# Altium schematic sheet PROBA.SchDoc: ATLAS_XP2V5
size 558 x 431 mm; Organization: IMP Automatika d.o.o.; Revision: V5
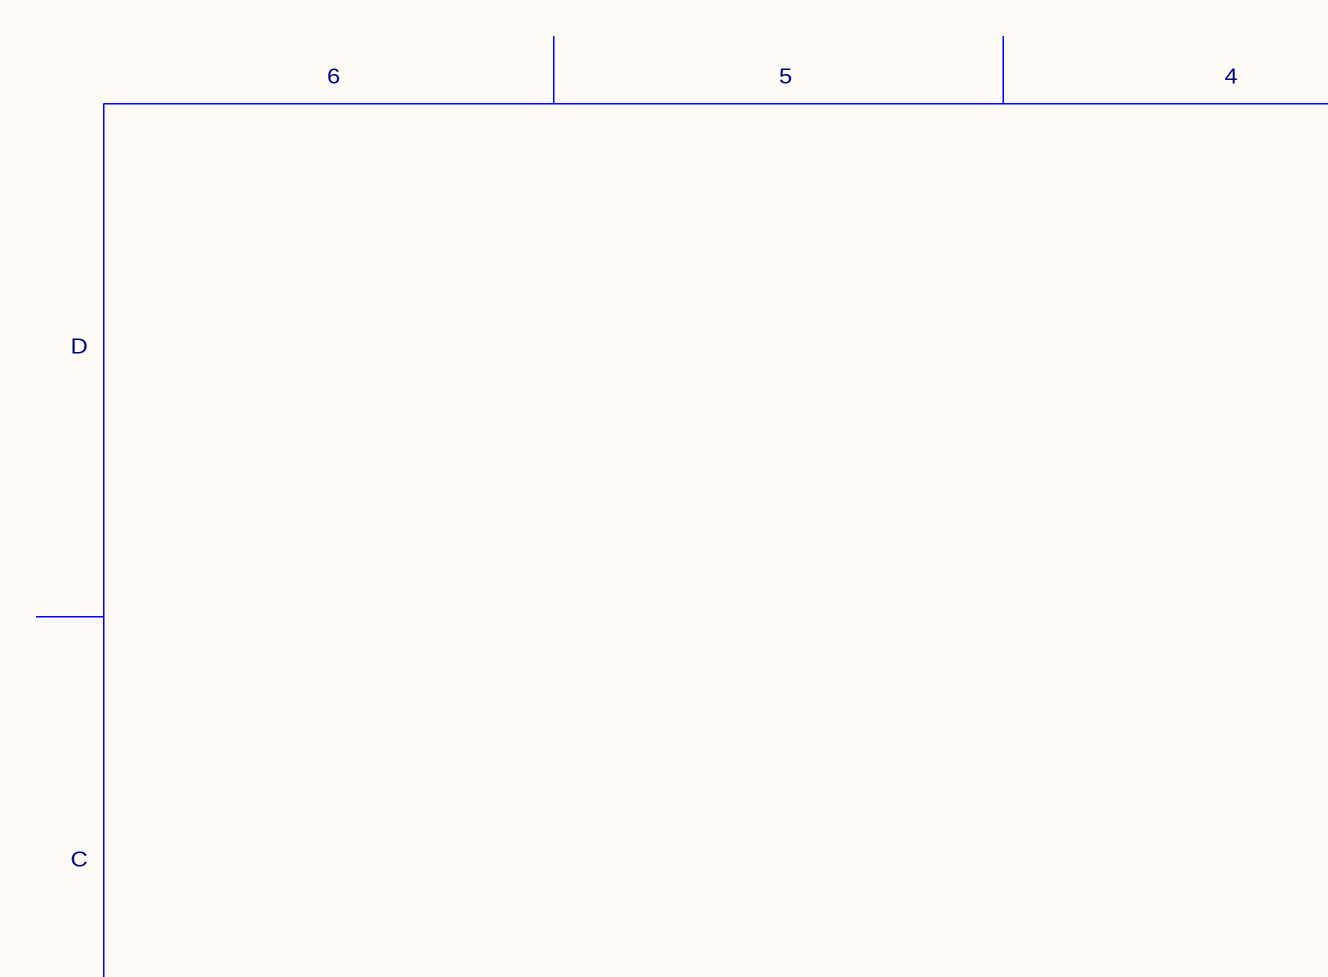
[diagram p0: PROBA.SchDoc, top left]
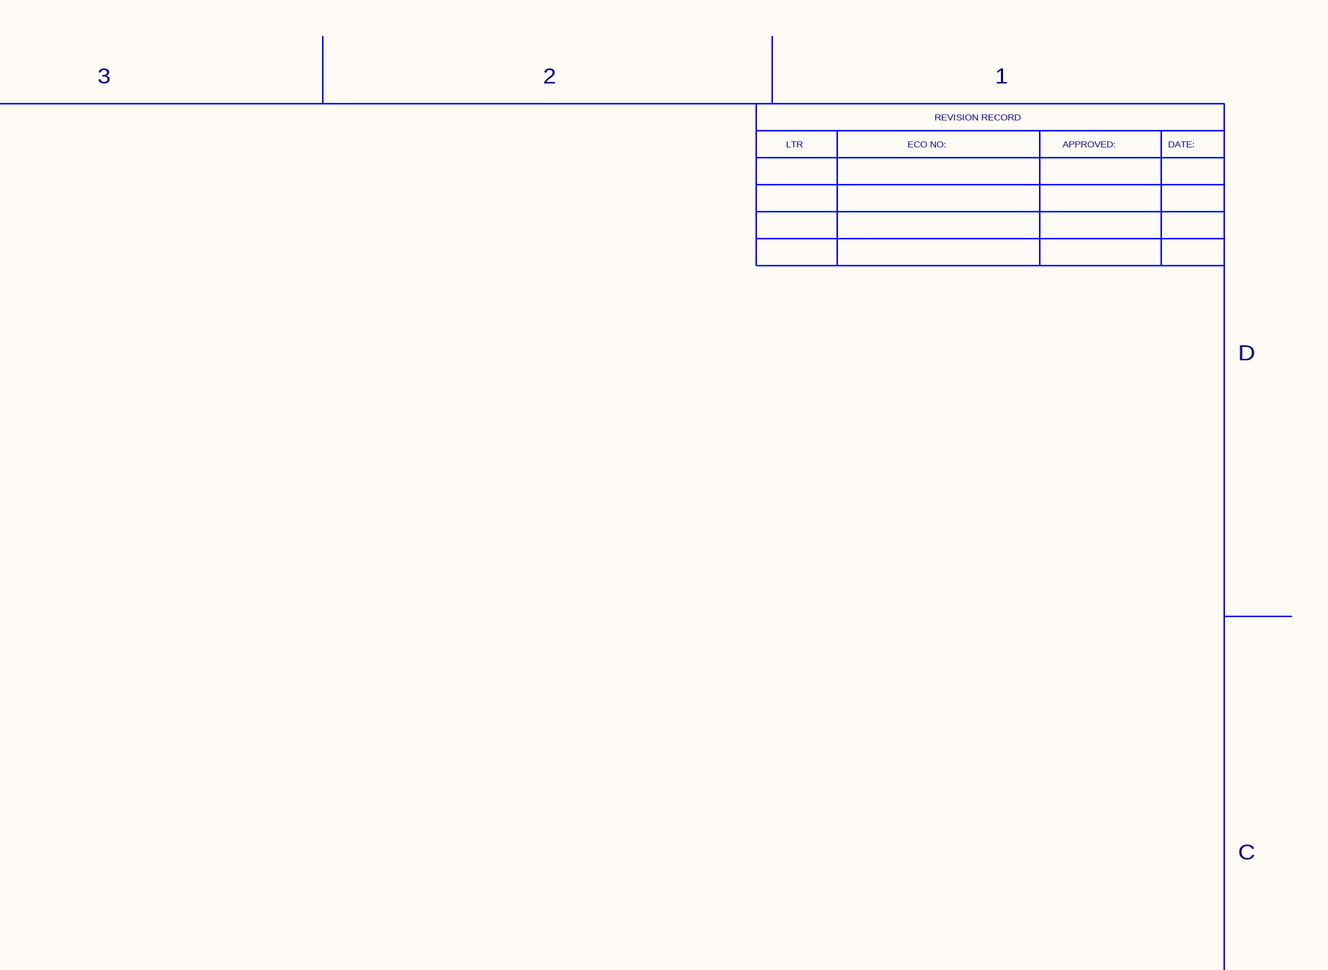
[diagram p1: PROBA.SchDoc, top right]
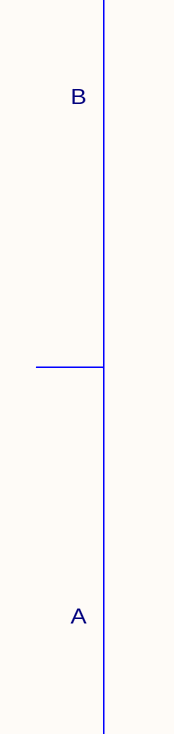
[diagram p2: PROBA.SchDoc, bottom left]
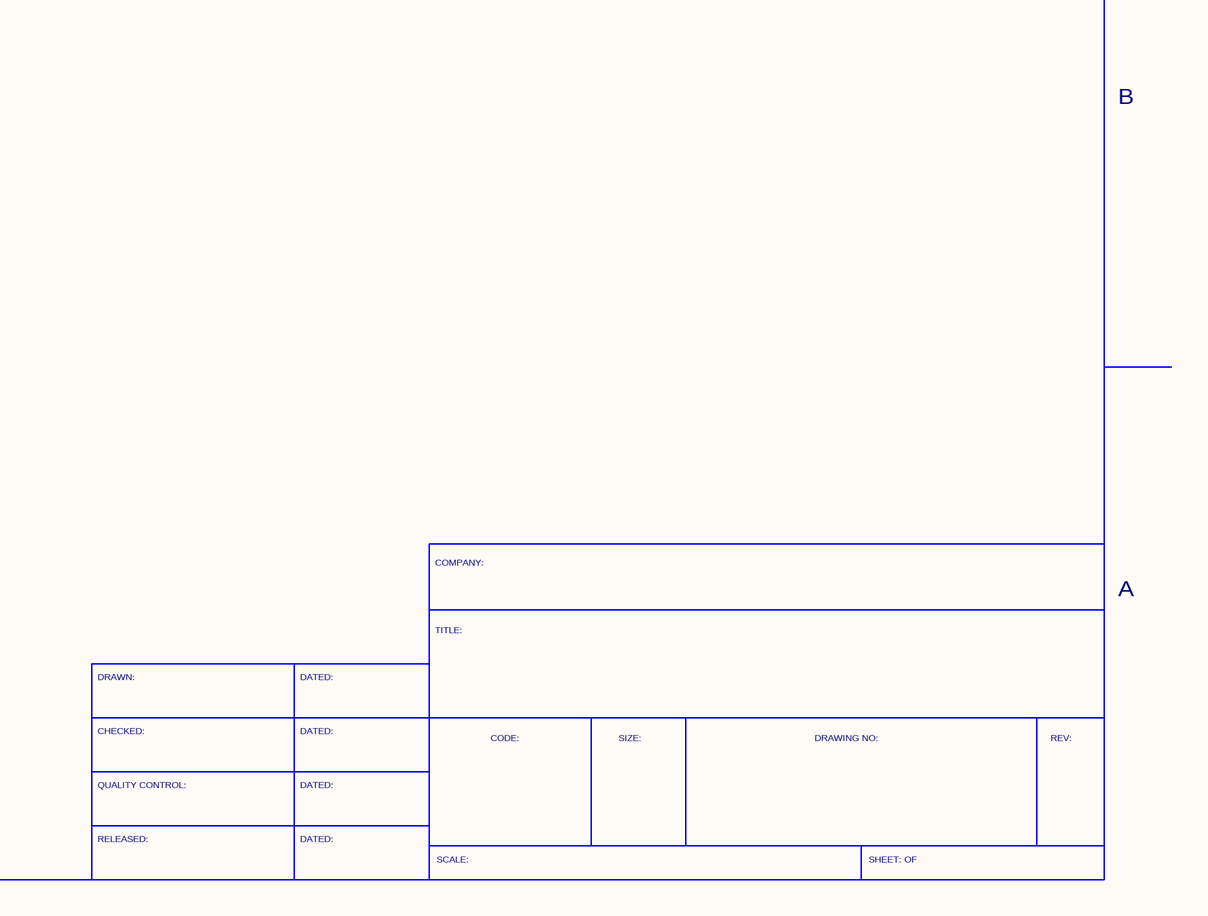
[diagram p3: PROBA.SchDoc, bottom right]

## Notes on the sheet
- 6
- 5
- 4
- 3
- 2
- 1
- LTR
- ECO NO:
- REVISION RECORD
- APPROVED:
- DATE:
- D
- C
- B
- COMPANY:
- A
- TITLE:
- DRAWN:
- DATED:
- CHECKED:
- CODE:
- SIZE:
- DRAWING NO:
- REV:
- QUALITY CONTROL:
- RELEASED:
- SCALE:
- SHEET: OF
